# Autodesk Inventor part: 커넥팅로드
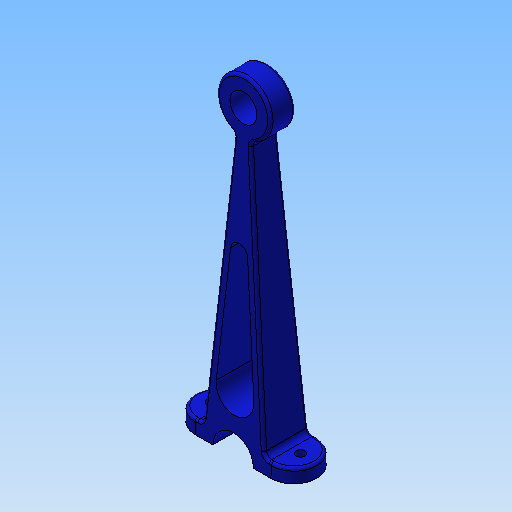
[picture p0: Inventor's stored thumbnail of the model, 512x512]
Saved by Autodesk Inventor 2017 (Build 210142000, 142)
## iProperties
Created: 2017-05
Part Number: 커넥팅로드
Material: 강철, 탄소
Document SubType Name: Modeling
Designer: mduedu
Density: 7.87 g/cm^3
Mass: 120.522 g
Surface Area: 85.3879 cm^2
Volume: 15.3141 cm^3
Appearance: 파란색 - 벽 페인트 - 무광
Author: mduedu
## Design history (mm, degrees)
sketch "스케치1"
  geometry: L1 (-22.5, 0)-(22.5, 0); L2 (22.5, 0)-(22.5, 5); L3 (-22.5, 5)-(-22.5, 0); L4 (-11.352, 5)-(-3, 100.461); L5 (0, 110)-(0, 0); L6 (11.352, 5)-(3, 100.461); L7 (22.5, 5)-(11.352, 5); L8 (-11.352, 5)-(-22.5, 5); C1 r 5 at (0, 110); A1 r 10 centre (0, 110) between (3, 100.461) and (-3, 100.461); 1 further point
  constraints: 16 end point, 4 parallel, 2 centre point, 2 coincident, 2 point on circle, 2 symmetric about line, 1 horizontal, 1 midpoint, 1 perpendicular, 1 vertical alignment
  dimensions: "d0" = 5 distance of L1.end L2.end; "d2" = 45 distance of L1.start L1.end; "d3" = 20 diameter of A1; "d4" = 10 diameter of C1; "d5" = 110 distance from line of L1 L5.start; "d6" = 5 deg angle of L5 L4; "d7" = 3 distance from line of L4.end L5
extrude "돌출1" new body sketch "스케치1" distance "d8" = 8.5; taper "d9" = 0 deg
sketch "스케치2"
  geometry: C1 r 7.5 at (0, 0); 1 further point
  constraints: 1 centre point, 1 coincident
  dimensions: "d10" = 15 diameter of C1
extrude "돌출2" cut sketch "스케치2" stored distance "d11" = 8.5; taper "d12" = 0 deg
sketch "스케치3"
  geometry: L1 (-3, 100.461)-(-11.352, 5) reference; L2 (11.352, 5)-(3, 100.461) reference; L3 (-3.154, 64.276)-(-6.975, 20.61); L4 (6.975, 20.61)-(3.154, 64.276); A1 r 3.166 centre (0, 64) between (3.154, 64.276) and (-3.154, 64.276); A2 r 7.001 centre (0, 20) between (-6.975, 20.61) and (6.975, 20.61); 1 further point
  constraints: 4 end point, 4 point on circle, 4 tangent, 2 centre point, 2 parallel, 1 vertical alignment
  dimensions: "d15" = 3 distance between parallel lines of L2 L4; "d16" = 44 distance of A2.centre A1.centre; "d17" = 20 distance of A2.centre point (0, 0)
extrude "돌출3" cut sketch "스케치3" stored distance "d18" = 8.5; taper "d19" = 0 deg
fillet "모깎기1" dims "d20" = 2
fillet "모깎기2" dims "d21" = 2
feature "면 기울기1" dims angle "d22" = 2 deg
fillet "모깎기3"
fillet "모깎기4"
fillet "모깎기5" dims "d28" = 1
sketch "스케치5"
  geometry: 3 further points
  constraints: 2 horizontal alignment
  dimensions: "d29" = 16.5 distance of point (-2.364, -7.36) point (14.136, -7.36); "d30" = 16.5 distance of point (30.636, -7.36) point (14.136, -7.36) (= d29)
sketch "스케치6"
  geometry: 2 further points
  constraints: 2 other
hole "구멍1" sketch "스케치6" at (-29.684, -7.36), (3.316, -7.36) diameter "d31" = 3.4; stored, may be unused: countersink angle "d35" = 90 deg, drill point angle "d37" = 0 deg; dims "d32" = 6, "d33" = 4, "d34" = 2, "d36" = 8
node "솔리드1"
mirror "대칭1"
other parameters: "d13" = 4, "d14" = 4
